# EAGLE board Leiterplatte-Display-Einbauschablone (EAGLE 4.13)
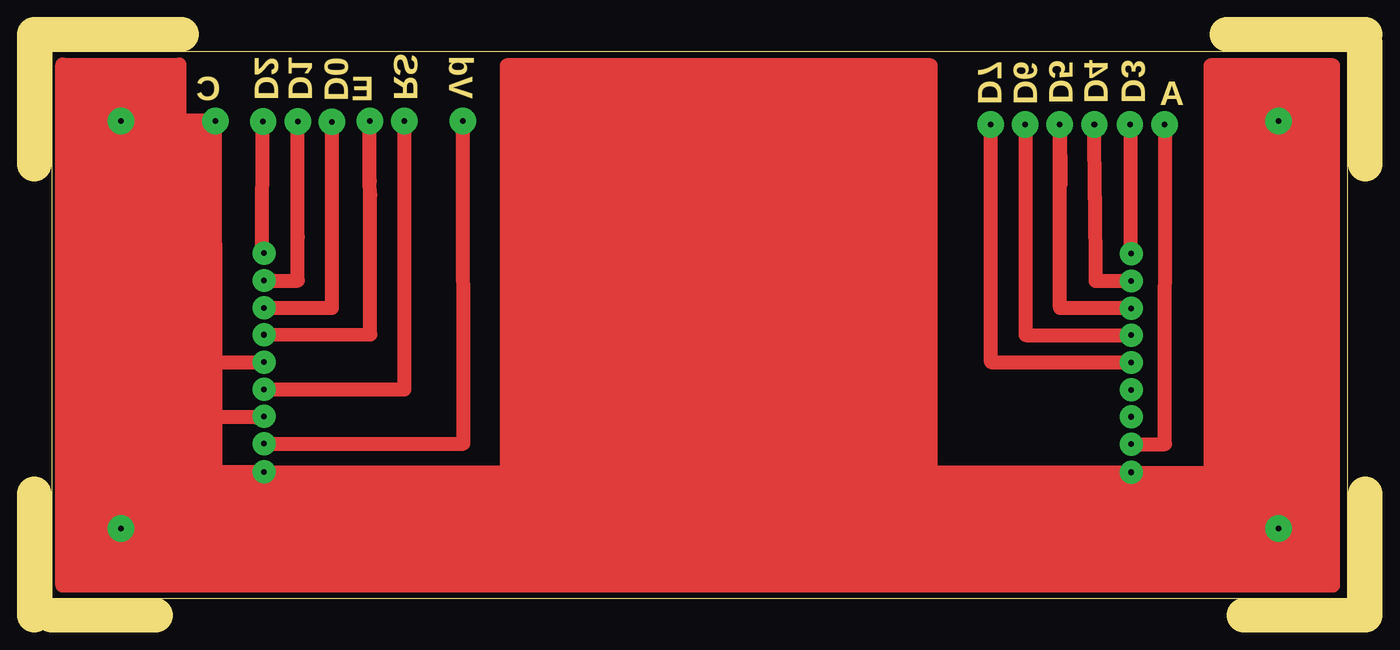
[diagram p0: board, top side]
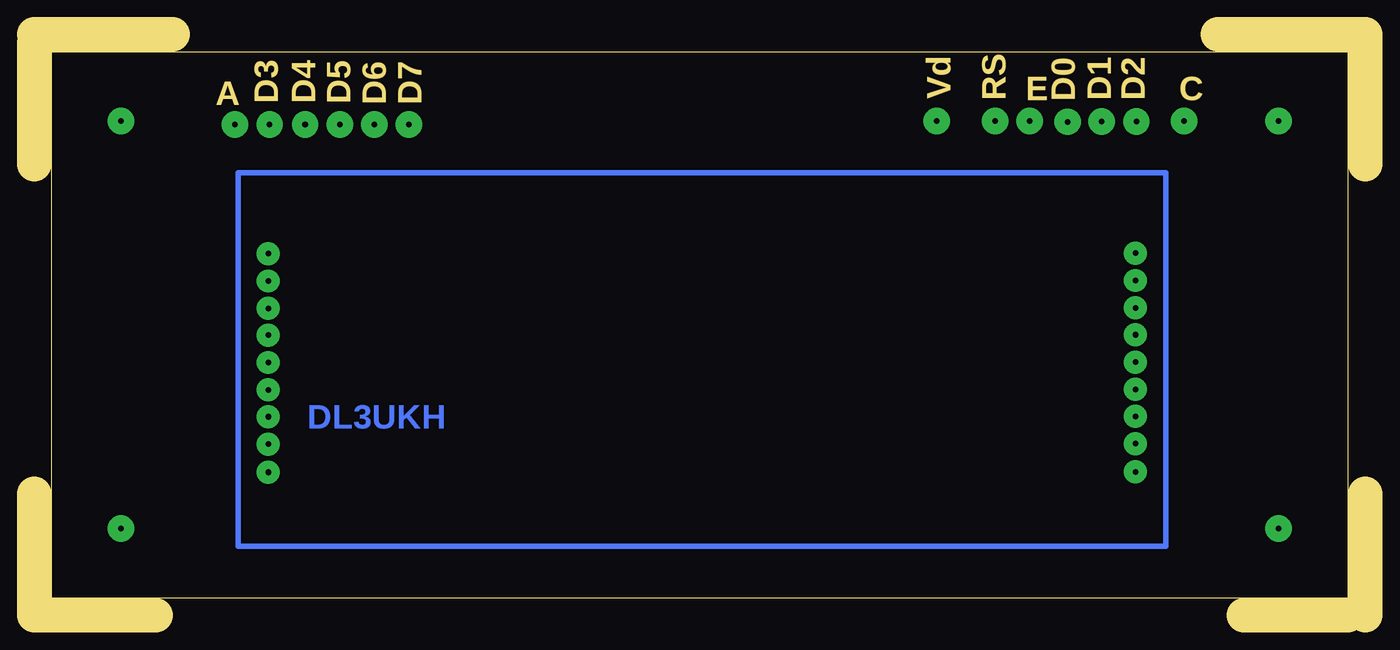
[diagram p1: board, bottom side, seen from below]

Size 97.47 x 42.55 mm. Coordinates in mm from the lower left corner, seen from the top.
Outline: 97.47,8.89 97.47,0 88.58,0
Outline: 97.47,41.91 97.47,33.02
Outline: 1.27,0 8.89,0
Outline: 0,0 0,8.89
Outline: 0,41.91 0,33.02
Outline: 97.47,42.55 87.31,42.55
Outline: 0,42.23 0,42.55 10.79,42.55
Outline: 96.2,41.28 1.27,41.28 1.27,1.27 96.2,1.27 96.2,41.28
Copper layers (1*16): Top 0.035mm / dielectric 1.5mm / Bottom 0.035mm
Design rules "default": minimum track width 10mil, minimum drill 24mil, track to track 8mil, track to pad 8mil, pad to pad 8mil, via to via 8mil, smd to smd 8mil, copper to edge 40mil, drill to drill 8mil, minimum pad ring 10mil, minimum via ring 8mil, stop-mask expansion 4mil, vias tented up to drill 0mil, thermal gap 10mil

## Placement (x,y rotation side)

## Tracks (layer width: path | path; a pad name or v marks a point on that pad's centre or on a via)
S$1
  Top 1.016: 13.3,18.51 13.27,36.07
S$2
  Bottom 0.406: 82.55,5.08 82.55,32.38 14.6,32.38 14.6,5.08 82.55,5.08
S$3  (via drill 0.41 pad 1.68, 0.41 pad 1.93)
  Top 1.016: v16.83,10.51 13.3,10.51 13.3,14.29 | 13.3,14.29 13.3,14.54 16.83,14.54 v16.83,14.57 | 16.8,18.54 13.3,18.54 13.3,14.29 | 80.26,10.48 v80.33,10.48 80.33,10.41 80.26,10.41 80.26,10.48 | 16.8,10.48 80.26,10.48 | v80.33,12.54 82.8,12.54 82.84,35.91 | 80.23,35.91 80.3,35.91 80.3,26.57 80.33,26.51 | 80.33,24.51 77.72,24.48 77.69,30.57 77.66,30.51 77.63,35.91 | 80.33,22.51 75.12,22.51 75.12,35.91 75.15,31.56 75.09,33.02 | v80.33,20.51 72.61,20.51 72.61,35.91 | 80.36,18.54 70.07,18.54 70.07,35.94 | 16.73,36.29 16.7,26.51 16.8,26.51 | 19.3,27.69 v19.3,36.16 | 19.3,27.69 | 19.3,27.69 19.3,24.51 v16.83,24.51 | v16.83,22.51 21.81,22.51 21.81,28.13 | v21.81,36.13 21.81,28.16 21.81,29.27 | v16.83,20.54 24.61,20.57 24.61,30.77 | 24.61,30.77 24.57,30.8 | v24.57,36.2 24.57,31.78 24.61,30.77 | v16.83,16.54 27.11,16.54 v27.11,36.2 | v16.83,12.57 31.43,12.57 31.4,36.13 | 31.31,36.1 31.34,35.94 31.31,36.04 | 80.39,10.41 86.14,10.41 86.14,40.26 95.12,40.26 95.12,2.19 2.06,2.19 2.06,40.32 10.64,40.32 10.64,36.23 13.21,36.23
  other vias: 16.83,18.54 16.83,26.51 91.12,6.35 91.12,36.2 6.35,36.2 6.35,6.35 80.33,14.54 80.33,16.51 80.33,18.51 80.33,22.48 80.33,24.48 80.33,26.48 82.77,35.94 80.23,35.94 77.63,35.94 75.09,35.94 72.55,35.94 70.04,35.94 13.27,36.2 16.76,36.16 31.4,36.2
S$4
  Top 1.016: 65.63,40.26 34.61,40.26 34.61,9.53
S$5
  Top 1.016: 65.63,40.16 65.63,9.72
(copper drawn outside any net)
  shapes: Top area x5

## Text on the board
Top: 95mm | 40mm
Bottom: DL3UKH
Dimension: Vd | C | D2 | D1 | D0 | E | RS | D7 | D6 | D5 | D4 | D3 | A
tOrigins: Auf Bestückungsseite gesehen ! | 4 Stck. | Distanzbolzen 5mm | lang | 9 | 10 | LCD-Modul oben | So wäre die | Zeit zu sehen | 23:05.00 | 1 | LCD-Modul unten | 18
